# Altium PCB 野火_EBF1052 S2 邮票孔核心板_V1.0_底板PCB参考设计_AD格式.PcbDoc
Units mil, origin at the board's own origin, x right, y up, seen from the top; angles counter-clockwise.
Board outline 50000 x 50000 mil, 2 copper layers (Signal, Signal #001), stack 10.4 mil thick; 1 components, 3 nets, 120 pads, 0 vias.
Unrouted connection lines stored in the file: 21.
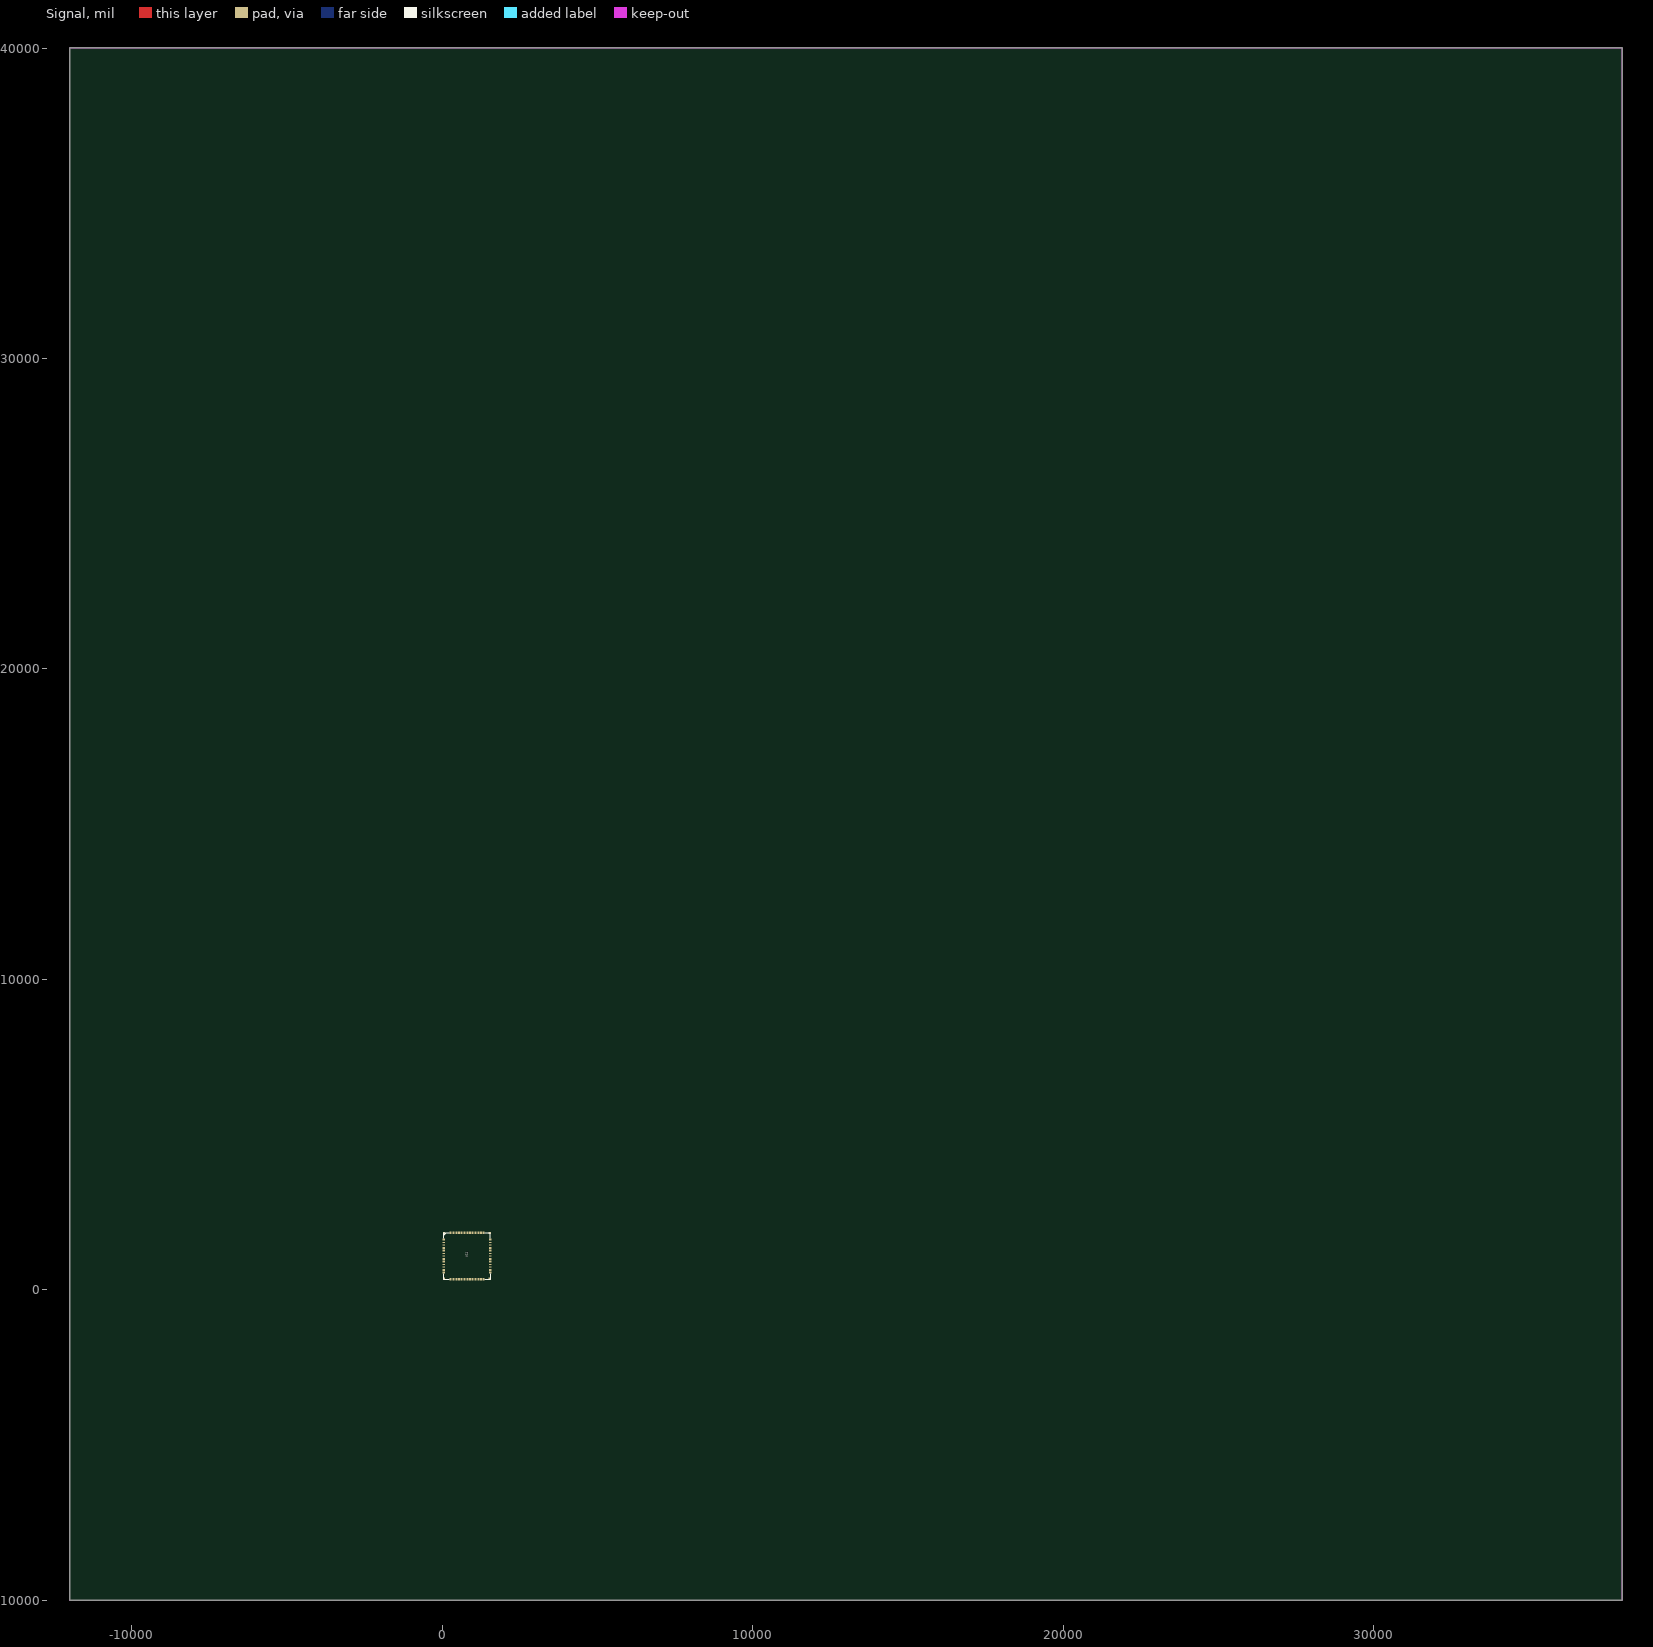
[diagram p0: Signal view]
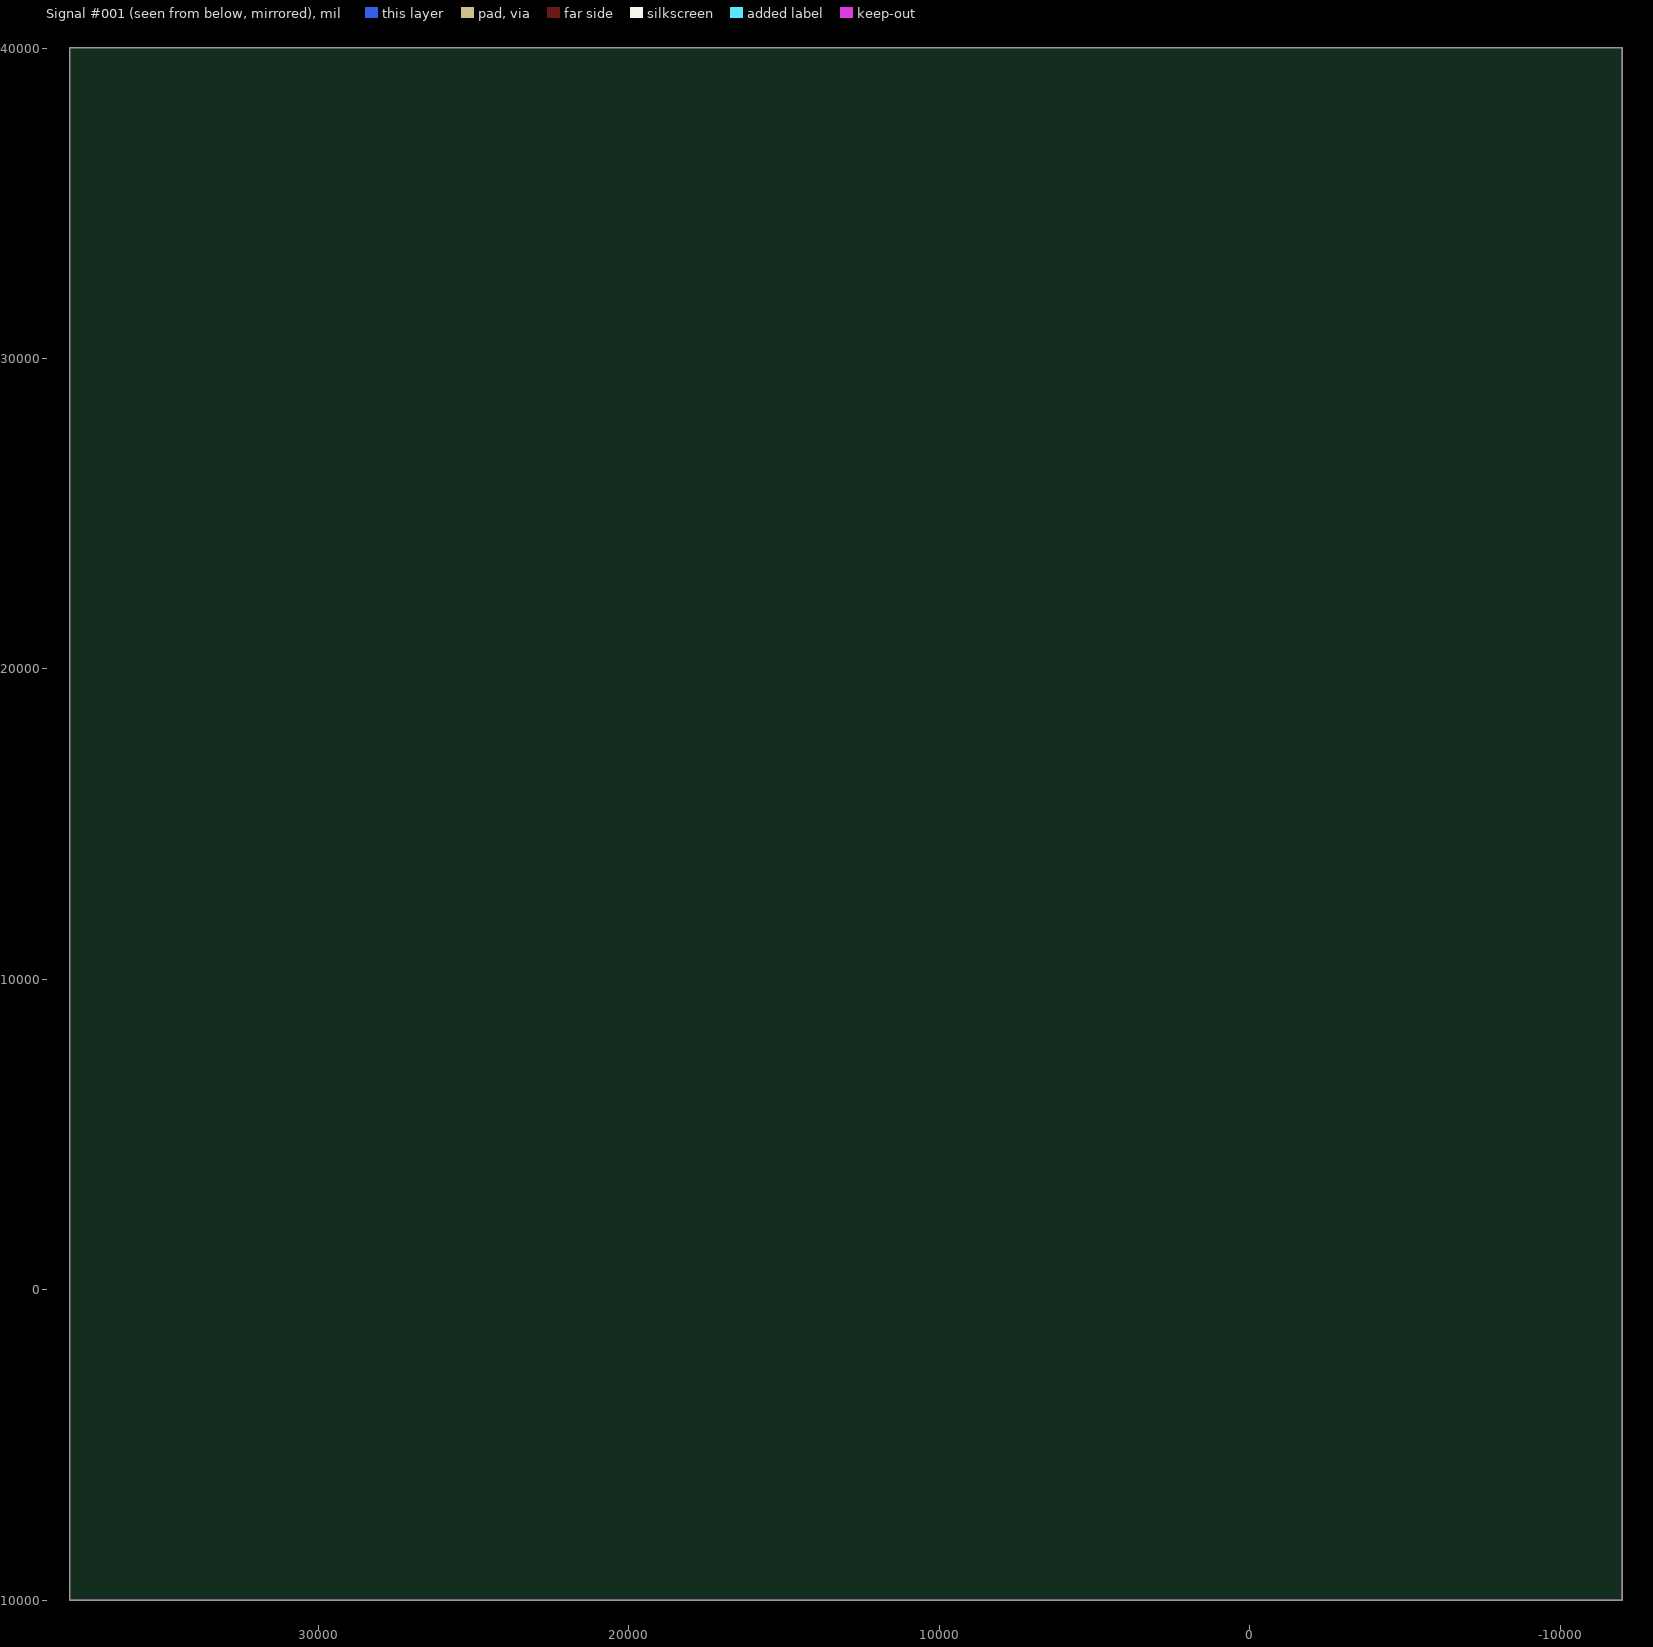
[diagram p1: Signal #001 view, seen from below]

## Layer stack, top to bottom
Solder Mask Top: solder mask 0.4, Solder Resist, Dk 3.5
Signal: signal copper 1.2
Dielectric 1: dielectric 8, FR-4, Dk 4.5
Signal #001: signal copper 1.2
Solder Mask Bottom: solder mask 0.4, Solder Resist, Dk 3.5

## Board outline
-11995,-9995 38005,-9995 38005,40005 -11995,40005

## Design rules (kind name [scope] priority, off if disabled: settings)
Clearance "Clearance - Default - DEFAULT - Via" [IsVia vs IsVia] p1: gap=5 ignorepadtopadclearanceinfootprint=FALSE
Clearance "Clearance - Default - DEFAULT- SMD" [IsVia vs IsSMTPin] p2: gap=5 ignorepadtopadclearanceinfootprint=FALSE
Clearance "Clearance - Default - DEFAULT - Net" [All] p3: gap=5 ignorepadtopadclearanceinfootprint=FALSE except(0: Arc-Hole Track-Hole SMDPad-Hole THPad-Hole Via-Hole Fill-Hole Poly-Hole Region-Hole Text-Hole; 3.79: Arc-Via Track-Via SMDPad-Via Via-Text; 3.94: Via-Fill Via-Poly Via-Region; 10: Fill-Fill Fill-Poly Fill-Region Poly-Poly Poly-Region Region-Region Text-Text)
ComponentClearance "ComponentClearance - Default - DEFAULT" [All] p1: gap=0 collisioncheckmode=3 verticalgap=10 showdistances=FALSE
FanoutControl Fanout_SOIC [IsSOIC] p1: bgadir=Out bgaviamode=Centered fanoutstyle=Auto fanoutdirection=Alternating viagrid=1 // Fanout_SOIC (Default Rule)
FanoutControl Fanout_Small [(CompPinCount < 5)] p2: bgadir=Out bgaviamode=Centered fanoutstyle=Auto fanoutdirection=OutThenIn viagrid=1 // Fanout_Small (Default Rule)
FanoutControl Fanout_LCC [IsLCC] p3: bgadir=Out bgaviamode=Centered fanoutstyle=Auto fanoutdirection=Alternating viagrid=1 // Fanout_LCC (Default Rule)
FanoutControl Fanout_BGA [IsBGA] p4: bgadir=Out bgaviamode=Centered fanoutstyle=Auto fanoutdirection=Alternating viagrid=1 // Fanout_BGA (Default Rule)
HoleToHoleClearance "HoleToHoleClearance - Default - DEFAULT" [All] p1: gap=8 allowstackedmicrovias=TRUE
Length "Default Length" [All] p1: maxlimit=50000 minlimit=0
MaxMinImpedance "Default Impedance" [All] p1: minimum=50.00 maximum=150.0
ParallelSegment "Default Parallel Segment Same Layer" [All] p1: limit=1000 gap=200
ParallelSegment "Default Parallel Segment Adjasent" [All] p2: limit=1000 gap=200
RoutingLayers "RoutingLayers - Default - DEFAULT" [All] p1: top layer_v5=TRUE bottom layer_v5=TRUE
RoutingPriority "RoutingPriority - Default - DEFAULT" [All] p1: routingpriority=3
RoutingTopology "Default Routing Topology" [All] p1: topology=Shortest
RoutingVias "RoutingVias - Default - DEFAULT" [All] p1: holewidth=37 width=55 viastyle="Through Hole" minholewidth=37 minwidth=55 maxholewidth=37 maxwidth=55
SMDToCorner "SMDToCorner - Default - DEFAULT" [All] p1: distance=50000
SolderMaskExpansion [All] p1: expansion=4
Width "Default Width" [All] p1: maxlimit=5 minlimit=5 preferedwidth=5
18 further rules are at their usual default settings.

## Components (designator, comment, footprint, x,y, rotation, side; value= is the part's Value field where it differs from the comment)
U11 "RT1052_SOM_S2_116P_38X38" RT1052_SOM_S2_116P_38X38 795,1090 r90 top

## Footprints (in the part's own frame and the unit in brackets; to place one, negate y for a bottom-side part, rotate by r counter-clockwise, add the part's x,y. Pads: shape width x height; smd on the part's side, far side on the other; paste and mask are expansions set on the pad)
RT1052_SOM_S2_116P_38X38 [mm]
  rect 0.6x2 smd mask+0.05: 1(14,19) 2(13,19) 3(12,19) 4(11,19) 5(10,19) 6(9,19) 7(8,19) 8(7,19) 9(6,19) 10(5,19) 11(4,19) 12(3,19) 13(2,19) 14(1,19) 15(0,19) 16(-1,19) 17(-2,19) 18(-3,19) 19(-4,19) 20(-5,19) 21(-6,19) 22(-7,19) 23(-8,19) 24(-9,19) 25(-10,19) 26(-11,19) 27(-12,19) 28(-13,19) 29(-14,19) 59(-14,-19) 60(-13,-19) 61(-12,-19) 62(-11,-19) 63(-10,-19) 64(-9,-19) 65(-8,-19) 66(-7,-19) 67(-6,-19) 68(-5,-19) 69(-4,-19) 70(-3,-19) 71(-2,-19) 72(-1,-19) 73(0,-19) 74(1,-19) 75(2,-19) 76(3,-19) 77(4,-19) 78(5,-19) 79(6,-19) 80(7,-19) 81(8,-19) 82(9,-19) 83(10,-19) 84(11,-19) 85(12,-19) 86(13,-19) 87(14,-19)
  rect 2x0.6 smd mask+0.05: 30(-19,14) 31(-19,13) 32(-19,12) 33(-19,11) 34(-19,10) 35(-19,9) 36(-19,8) 37(-19,7) 38(-19,6) 39(-19,5) 40(-19,4) 41(-19,3) 42(-19,2) 43(-19,1) 44(-19,0) 45(-19,-1) 46(-19,-2) 47(-19,-3) 48(-19,-4) 49(-19,-5) 50(-19,-6) 51(-19,-7) 52(-19,-8) 53(-19,-9) 54(-19,-10) 55(-19,-11) 56(-19,-12) 57(-19,-13) 58(-19,-14) 88(19,-14) 89(19,-13) 90(19,-12) 91(19,-11) 92(19,-10) 93(19,-9) 94(19,-8) 95(19,-7) 96(19,-6) 97(19,-5) 98(19,-4) 99(19,-3) 100(19,-2) 101(19,-1) 102(19,0) 103(19,1) 104(19,2) 105(19,3) 106(19,4) 107(19,5) 108(19,6) 109(19,7) 110(19,8) 111(19,9) 112(19,10) 113(19,11) 114(19,12) 115(19,13) 116(19,14)
  rect 2x2 smd mask+0.05: 117(18.8,18.8) 118(-18.8,18.8) 119(-18.8,-18.8) 120(18.8,-18.8)
  silkscreen extent -19,-19.01 19.06,19.02

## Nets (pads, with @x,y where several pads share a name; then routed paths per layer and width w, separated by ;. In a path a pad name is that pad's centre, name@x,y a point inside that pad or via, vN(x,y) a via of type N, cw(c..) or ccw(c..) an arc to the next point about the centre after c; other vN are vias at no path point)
5V_SYS: U11.83 U11.87
DCDC_3V3: U11.113 U11.114 U11.115
GND: U11.28 U11.30 U11.37 U11.44 U11.51 U11.58 U11.66 U11.74 U11.80 U11.84 U11.88 U11.109 U11.110 U11.111 U11.112 U11.117 U11.118 U11.119 U11.120
pads on no net: U11.1 U11.2 U11.3 U11.4 U11.5 U11.6 U11.7 U11.8 U11.9 U11.10 U11.11 U11.12 U11.13 U11.14 U11.15 U11.16 U11.17 U11.18 U11.19 U11.20 U11.21 U11.22 U11.23 U11.24 U11.25 U11.26 U11.27 U11.29 U11.31 U11.32 U11.33 U11.34 U11.35 U11.36 U11.38 U11.39 U11.40 U11.41 U11.42 U11.43 U11.45 U11.46 U11.47 U11.48 U11.49 U11.50 U11.52 U11.53 U11.54 U11.55 U11.56 U11.57 U11.59 U11.60 U11.61 U11.62 U11.63 U11.64 U11.65 U11.67 U11.68 U11.69 U11.70 U11.71 U11.72 U11.73 U11.75 U11.76 U11.77 U11.78 U11.79 U11.81 U11.82 U11.85 U11.86 U11.89 U11.90 U11.91 U11.92 U11.93 U11.94 U11.95 U11.96 U11.97 U11.98 U11.99 U11.100 U11.101 U11.102 U11.103 U11.104 U11.105 U11.106 U11.107 U11.108 U11.116

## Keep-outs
Keep-Out Layer:
  the board outline again, w10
